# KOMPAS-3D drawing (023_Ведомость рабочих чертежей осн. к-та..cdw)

Referenced files in C:\Documents and Settings\nastya\Рабочий стол\Проекты г.Альметьевкс\: 3 Ведомость рабочих чертежей осн. к-та.cdw
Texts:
  ПСПД-0000-2015
  Zver
  Microsoft
  ПСПД-0000-2015 План подключения потребителя к тепловой сети
  ПСПД-0000-2015 Ситуационный план
  ГИП
  Пров.
  Разраб.
  Ведомость рабочих чертежей
  ЗАО "ПромСервис"
  ПСПД-0000-2015 Принципиальная схема
  ПСПД-0000-2015 Функциональная схема
  ПСПД-0000-2015 План размещения оборудования и внешних проводок
  ПСПД-0000-2015 Кабельный журнал
  ПСПД-0000-2015 Сводная спецификация оборудования, изделий и материалов
  ПСПД-0000-2015 Монтажный чертеж
  ПСКД.25.5422.000.01 Э4 Шкаф связи и управления ШСУ-54-22-01 Схема электрических соединений
  ПСКД.25.5422.000.01 СБ Шкаф связи и управления ШСУ-54-22-01  Сборочный чертеж
  ПСПД-0000-2015 Установка термопреобразователя на трубу Ду65 (d76х5,5)
  ПСПД-0000-2015 Схема пломбировки преобразователя расхода ЭМИР-ПРАМЕР-550
  ПСПД-0000-2015 Пломбировка термопреобразователя
  ПСПД-0000-2015 Схема установки датчика давления мод. ПД-Р с радиатором-охлодителей
  ПСПД-0000-2015 Схема пломбировки датчика давления мод. ПД-Р
  Ведомость рабочих чертежей ОК. Ведомость спецификаций. Первый лист. ГОСТ Р 21.1101-2009 Ф1
  Лит-Масса-Масштаб
  Материал-Предприятие
  Title Specification
  Body Specification ( left align )
  Body Specificaton ( centered )
  Лист
  Подпись лица, копировавшего чертеж
  Обозначение формата листа
  Инв. № подл.
  Подп. и дата
  Взам. инв. №
  Инвентарный номер подлинника
  Подпись принявшего подлинник в отдел технической документации
  Инвентарный номер подлинника, взамен которого выпущен данный подлинник
  Согласовано
  Подпись
  Изм.
  Кол.уч.
  № док.
  Подп.
  Дата
  Листов
  Стадия
  Порядковый номер изменения документа
  Количество изменяемых участков
  Обозначение разрешения
  Наименование документа
  Порядковый номер листа
  Количество листов документа
  Наименование (различительный индекс) предприятия, выпускающего документ
  Таблица ведомости
  Таблица согласований
Dimensions and other numbers on the sheet: 1:1; 06-03/11-Пк-ОВ-; 1; 20; 21; 22; 23; 24; 25; 26; 27; 28; 29; 32; 2 листа; 34; 35; 36; 3 листа; 37; 38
